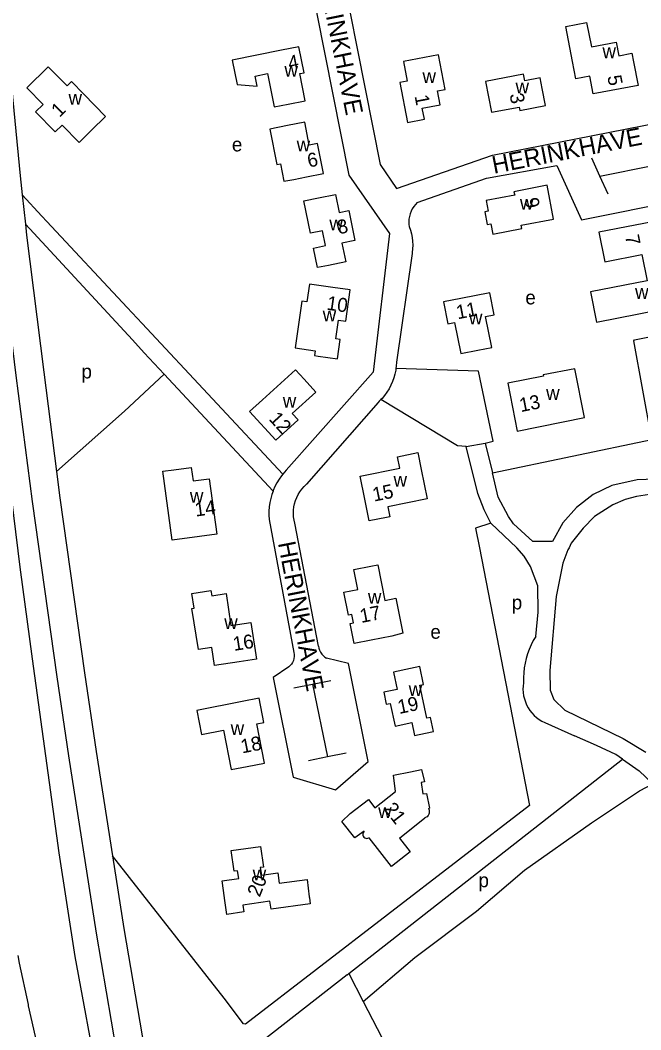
# Model space of a CAD drawing. Extents: x 157646 to 159241, y 379213 to 381217.
# Drawn here: x 158061.7 to 158238.9, y 379962.3 to 380250.8 of the extents above; entities that cross this region are included whole.
import ezdxf

# ---------------------------------------------------------------- set-up
doc = ezdxf.new("R2010")
doc.units = 0
for name, color, linetype in [('BLT_Basislijn', 7, 'Continuous'), ('BLT_Bebouwing', 7, 'Continuous'), ('BLT_Centroide', 7, 'Continuous'), ('BLT_Huisnummer', 7, 'Continuous'), ('BLT_Spoorlijn', 7, 'Continuous'), ('BLT_Straatnaam', 7, 'Continuous')]:
    doc.layers.add(name, color=color, linetype=linetype)

msp = doc.modelspace()

# ---------------------------------------------------------------- linework, layer by layer
at = {"layer": 'BLT_Basislijn'}
for p, q in [((158227.22, 380206.29), (158224.91, 380211.44)), ((158227.22, 380206.29), (158242.34, 380209.26)), ((158229.53, 380201.14), (158227.22, 380206.29)), ((158062.28, 380200.88), (158067.86, 380194.86)), ((158063.19, 380192.51), (158093.73, 380159.46)), ((158173.6, 380184.14), (158169.11, 380153.05)), ((158096.52, 380164.1), (158092.22, 380168.71)), ((158096.52, 380164.1), (158136.64, 380121.05)), ((158093.73, 380159.46), (158097.13, 380155.79)), ((158097.13, 380155.79), (158102.75, 380149.7)), ((158102.75, 380149.7), (158133.89, 380116.21)), ((158163.86, 380141.58), (158143.41, 380118.21)), ((158189.01, 380128.98), (158194.49, 380129.98)), ((158194.49, 380129.98), (158196.52, 380121.45)), ((158132.79, 380108.13), (158139.85, 380070.1)), ((158146.87, 380071.93), (158140.11, 380107.03)), ((158139.84, 380060.01), (158145.12, 380061.08)), ((158145.12, 380061.08), (158150.41, 380062.15)), ((158145.12, 380061.08), (158149.41, 380040.26)), ((158211.45, 380050.09), (158219.92, 380046.29)), ((158149.41, 380040.26), (158144.04, 380039.15)), ((158154.78, 380041.37), (158149.41, 380040.26)), ((158155.49, 379978.39), (158233.7, 380039.58)), ((158155.01, 379978.02), (158155.49, 379978.39)), ((158155.49, 379978.39), (158159.66, 379970.33))]:
    msp.add_line(p, q, dxfattribs=at)
for points in [[(158240.91, 380309.41), (158153.5, 380292.29), (158150.86, 380290.66), (158149.82, 380288.98), (158149.37, 380286.11), (158164.48, 380209.59), (158169.09, 380202.74), (158196.52, 380212.25), (158244.17, 380221.61), (158245.75, 380221.43)], [(158069.03, 380277.5), (158083.13, 380279.81), (158136.26, 380289.77), (158137.69, 380289.51), (158139.57, 380287.29), (158155.57, 380206.56), (158167.15, 380189.83), (158162.48, 380150.24), (158137.6, 380122.25), (158136.64, 380121.05)], [(158043.52, 380272.26), (158043.86, 380272.1), (158045.23, 380270.58), (158046.3, 380268.97), (158047.18, 380265.9), (158048.5, 380256.56), (158050.97, 380233.98), (158053.72, 380205.54), (158055.59, 380188.47), (158060.48, 380149.25), (158065.1, 380113.27), (158072.13, 380063.15), (158075.51, 380040.61), (158083.37, 379989.94), (158090.54, 379947.99)], [(158026.51, 380266.17), (158028.27, 380266.84), (158030.04, 380266.89), (158032.44, 380266.09), (158034.37, 380265.02), (158036.46, 380263.3), (158038.06, 380261.59), (158039.72, 380259.45), (158040.69, 380257.15), (158041.27, 380254.63), (158042.46, 380248.09), (158043.78, 380238.44), (158049.4, 380191.53), (158053.5, 380162.19), (158056.77, 380134.16), (158061.6, 380094.53), (158065.06, 380068.3), (158072.73, 380012.87), (158077.32, 379983.19), (158084.04, 379946.64)], [(158057.05, 380251.88), (158058.92, 380234.8), (158061.68, 380206.36), (158062.28, 380200.88)], [(158175.08, 380198.75), (158194.87, 380205.7), (158214.96, 380209.27)], [(158214.96, 380209.27), (158221.94, 380193.81), (158249.9, 380199.36)], [(158062.28, 380200.88), (158063.19, 380192.51)], [(158175.08, 380198.75), (158174.54, 380198.19), (158174.06, 380197.58), (158173.64, 380196.92), (158173.29, 380196.22), (158173.02, 380195.49), (158172.82, 380194.74), (158172.7, 380193.97), (158172.66, 380193.19), (158172.7, 380192.41), (158172.77, 380191.88)], [(158063.19, 380192.51), (158063.53, 380189.4), (158068.42, 380150.25), (158072.06, 380121.85)], [(158172.77, 380191.88), (158173.13, 380190.85), (158173.41, 380189.8), (158173.62, 380188.73), (158173.74, 380187.65), (158173.79, 380186.56), (158173.75, 380185.48), (158173.64, 380184.4), (158173.6, 380184.14)], [(158252.02, 380188.88), (158254.72, 380189.05), (158267, 380174.97), (158276.24, 380134.94), (158276.4, 380131.39), (158275.6, 380128.08), (158274.74, 380126.06), (158271.38, 380122.59), (158269.65, 380121.6), (158265.83, 380120.49), (158237.83, 380119.46), (158230.6, 380117.88), (158225.26, 380115.24), (158220.55, 380111.55), (158216.66, 380107.13), (158213.64, 380101.81), (158208.07, 380101.88), (158202.57, 380106.87), (158201.14, 380108.94), (158198.2, 380114.5), (158196.52, 380121.45)], [(158196.52, 380121.45), (158242.06, 380130.99), (158236.87, 380159.15), (158237.09, 380159.44), (158256.73, 380163.42), (158252.02, 380188.88)], [(158169.11, 380153.05), (158169.04, 380151.92), (158168.96, 380151.28)], [(158168.96, 380151.28), (158168.9, 380150.79), (158168.67, 380149.68), (158168.37, 380148.59), (158167.98, 380147.53), (158167.53, 380146.49), (158167, 380145.49), (158166.41, 380144.53), (158165.74, 380143.61), (158165.02, 380142.74), (158164.69, 380142.4)], [(158194.49, 380129.98), (158196.78, 380130.51), (158192.51, 380150.53), (158168.96, 380151.28)], [(158072.06, 380121.85), (158091.43, 380139.11), (158102.75, 380149.7)], [(158164.69, 380142.4), (158164.23, 380141.92), (158163.86, 380141.58)], [(158189.01, 380128.98), (158186.53, 380129.2), (158164.69, 380142.4)], [(158196.11, 380107.12), (158194.17, 380110.84), (158192.32, 380115.56), (158189.01, 380128.98)], [(158072.06, 380121.85), (158073.03, 380114.33), (158080.05, 380064.3), (158083.42, 380041.81), (158088.04, 380011.99)], [(158136.64, 380121.05), (158136.29, 380120.61), (158135.6, 380119.62), (158134.98, 380118.59), (158134.43, 380117.52), (158133.96, 380116.41), (158133.89, 380116.21)], [(158140.11, 380107.03), (158139.9, 380107.95), (158139.77, 380108.88), (158139.72, 380109.83), (158139.75, 380110.77), (158139.86, 380111.71), (158140.05, 380112.63), (158140.32, 380113.54), (158140.66, 380114.42), (158141.08, 380115.26), (158141.57, 380116.07), (158142.12, 380116.84), (158142.74, 380117.55), (158143.41, 380118.21)], [(158133.89, 380116.21), (158133.56, 380115.28), (158133.23, 380114.12), (158132.98, 380112.94), (158132.81, 380111.75), (158132.72, 380110.55), (158132.71, 380109.34), (158132.79, 380108.13)], [(158258.47, 380113.78), (158249.44, 380115.32), (158243.87, 380115.64), (158237.7, 380114.73), (158234.45, 380113.83), (158230.89, 380112.35), (158225.71, 380109), (158222.48, 380105.68), (158219.05, 380101.4), (158218.42, 380100), (158218.07, 380099.46), (158216.63, 380095.66), (158214.74, 380086.13), (158212.9, 380064.97), (158212.98, 380059.38), (158214.1, 380056.68), (158217.18, 380053.65), (158233.88, 380045.54), (158240.33, 380041.62)], [(158196.11, 380107.12), (158191.69, 380105.69), (158192.81, 380100), (158207.1, 380026.36), (158126.05, 379963.89), (158125.42, 379963.95), (158119.92, 379971.36), (158088.04, 380011.99)], [(158208.88, 380074.7), (158209.56, 380081.61), (158209.48, 380089.12), (158207.36, 380094.68), (158205.63, 380097.68), (158203.48, 380100), (158196.11, 380107.12)], [(158146.87, 380071.93), (158146.99, 380071.33), (158147.18, 380070.74), (158147.45, 380070.19), (158147.79, 380069.68), (158148.19, 380069.21), (158148.64, 380068.8), (158149.15, 380068.46)], [(158208.88, 380074.7), (158208.2, 380073.5), (158207.58, 380072.27), (158207.03, 380071), (158206.56, 380069.71), (158206.17, 380068.39), (158205.85, 380067.05), (158205.61, 380065.69), (158205.45, 380064.32), (158205.37, 380062.94), (158205.36, 380061.56), (158205.37, 380061.43)], [(158139.85, 380070.1), (158139.93, 380069.53), (158139.93, 380068.95), (158139.85, 380068.38), (158139.68, 380067.83), (158139.45, 380067.3), (158139.15, 380066.81), (158138.77, 380066.37), (158138.35, 380065.98)], [(158138.35, 380065.98), (158133.92, 380063), (158139.6, 380034.49), (158151.73, 380030.89), (158161.02, 380038.94), (158155.39, 380067), (158149.15, 380068.46)], [(158205.37, 380061.43), (158205.26, 380060.51), (158205.24, 380059.59), (158205.3, 380058.67), (158205.43, 380057.75), (158205.64, 380056.86), (158205.93, 380055.98), (158206.3, 380055.13), (158206.74, 380054.32), (158207.24, 380053.55), (158207.82, 380052.83), (158208.45, 380052.15), (158209.13, 380051.54), (158209.87, 380050.98), (158210.65, 380050.5), (158211.45, 380050.09)], [(158233.7, 380039.58), (158231.75, 380040.93), (158226.29, 380043.51), (158219.92, 380046.29)], [(158233.7, 380039.58), (158238.4, 380036.33), (158242.35, 380032.59)], [(158159.66, 379970.33), (158174.35, 379982.97), (158191.97, 379996.18), (158205.72, 380007.86), (158224.81, 380021.43), (158238.51, 380030.61), (158242.35, 380032.59)], [(158088.04, 380011.99), (158091.26, 379991.23), (158098.41, 379949.44), (158101.11, 379935.8)], [(158072.5, 379932.76), (158071.31, 379937.57), (158070.15, 379942.39), (158069.57, 379944.86), (158067.13, 379955.38), (158066.77, 379956.99), (158064.09, 379969.16), (158064.01, 379969.53), (158061.53, 379981.35), (158061.1, 379983.47)], [(158155.01, 379978.02), (158101.11, 379935.8)], [(158159.66, 379970.33), (158186.48, 379918.51), (158201.95, 379874.84), (158218.42, 379836.26)]]:
    msp.add_lwpolyline(points, dxfattribs=at)
at = {"layer": 'BLT_Bebouwing'}
for p, q in [((158112.87, 380103.23), (158105.07, 380102.17)), ((158170, 380017.04), (158177.23, 380022.87))]:
    msp.add_line(p, q, dxfattribs=at)
for points in [[(158236.85, 380238.9), (158238.13, 380232.21), (158225.27, 380229.74), (158224.3, 380234.84), (158220.37, 380234.08), (158219.42, 380238.99), (158217.5, 380249.03), (158223.43, 380250.17), (158224.77, 380243.18), (158231.87, 380244.54), (158232.62, 380240.66), (158236.37, 380241.38), (158236.85, 380238.9)], [(158138.19, 380226.84), (158143.09, 380227.82), (158141.55, 380235.56), (158142.73, 380235.8), (158141.24, 380243.24), (158136.34, 380242.26), (158122.25, 380239.45), (158123.66, 380232.42), (158129.39, 380231.93), (158128.81, 380234.88), (158132.34, 380235.59), (158134.24, 380226.05), (158138.19, 380226.84)], [(158171.13, 380238.99), (158172.2, 380233.43), (158170.07, 380233.02), (158172.25, 380221.62), (158177.09, 380222.55), (158176.49, 380225.67), (158181.62, 380226.65), (158180.85, 380230.65), (158183.03, 380231.07), (158181.14, 380240.91), (158171.13, 380238.99)], [(158082.08, 380219.39), (158078.5, 380215.9), (158073.65, 380220.85), (158071.66, 380218.89), (158066.05, 380224.62), (158068.24, 380226.76), (158063.6, 380231.49), (158069.71, 380237.48), (158075.05, 380232.03), (158076.33, 380233.28), (158079.82, 380229.71), (158086.08, 380223.32), (158082.08, 380219.39)], [(158210.76, 380231.35), (158210.18, 380234.32), (158205.76, 380233.47), (158205.39, 380235.4), (158194.57, 380233.32), (158196.26, 380224.5), (158204.17, 380226.02), (158204.36, 380225.03), (158211.7, 380226.44), (158210.76, 380231.35)], [(158143.39, 380206.03), (158148.3, 380207.01), (158146.58, 380215.63), (158144.23, 380215.16), (158142.93, 380221.67), (158138.03, 380220.69), (158132.94, 380219.68), (158134.96, 380209.56), (158136.01, 380209.77), (158137, 380204.78), (158139.81, 380205.32), (158143.39, 380206.03)], [(158214.01, 380194.01), (158212.16, 380203.64), (158202.68, 380201.82), (158202.88, 380200.83), (158194.76, 380199.27), (158195.35, 380196.21), (158194.36, 380196.02), (158195.05, 380192.45), (158196.06, 380192.65), (158196.63, 380189.69), (158204.93, 380191.28), (158204.75, 380192.24), (158214.01, 380194.01)], [(158149.74, 380180.76), (158146.55, 380180.11), (158145.41, 380185.71), (158148.87, 380186.42), (158148.01, 380190.62), (158144.58, 380189.92), (158142.72, 380199.22), (158146.84, 380200.04), (158151.75, 380201.02), (158152.77, 380195.9), (158155.51, 380196.45), (158157.23, 380187.83), (158153.56, 380187.08), (158154.64, 380181.76), (158149.74, 380180.76)], [(158246.1, 380188.86), (158245.14, 380193.77), (158226.94, 380190.21), (158228.6, 380181.74), (158239.23, 380183.82), (158240.7, 380176.33), (158224.56, 380173.18), (158226.24, 380164.57), (158249.94, 380169.21), (158246.1, 380188.86)], [(158152.25, 380154.03), (158153.05, 380159.6), (158151.84, 380159.77), (158152.61, 380165.13), (158154.66, 380164.84), (158155.94, 380173.73), (158150.99, 380174.44), (158144.29, 380175.41), (158143.55, 380170.31), (158142.11, 380170.51), (158140.2, 380157.19), (158145.91, 380156.37), (158145.71, 380154.97), (158146.77, 380154.81), (158152.25, 380154.03)], [(158192.37, 380156.51), (158196.33, 380157.24), (158194.59, 380166.15), (158197.04, 380166.63), (158195.82, 380172.9), (158187.5, 380171.27), (158182.59, 380170.31), (158183.81, 380164.09), (158185.72, 380164.46), (158187.46, 380155.55), (158192.37, 380156.51)], [(158142.77, 380148.22), (158140.34, 380150.91), (158130.9, 380142.36), (158127.2, 380139.01), (158134.64, 380130.79), (158141.04, 380136.59), (158139.39, 380138.41), (158146.13, 380144.51), (158142.77, 380148.22)], [(158211.01, 380149.46), (158211.08, 380149.09), (158200.95, 380147.11), (158203.62, 380133.39), (158222.84, 380137.25), (158220.1, 380151.23), (158211.01, 380149.46)], [(158176.2, 380122.37), (158177.9, 380114.06), (158166.64, 380111.76), (158167.22, 380108.91), (158166.25, 380108.71), (158161.35, 380107.71), (158160.08, 380113.97), (158158.77, 380120.48), (158170.06, 380122.78), (158169.39, 380126.08), (158175.2, 380127.27), (158176.2, 380122.37)], [(158105.07, 380102.17), (158102.44, 380121.9), (158105.59, 380122.33), (158110.54, 380123.01), (158111.07, 380119.15), (158115.66, 380119.78), (158117.83, 380103.9), (158112.87, 380103.23)], [(158161.94, 380073.64), (158157.03, 380072.68), (158155.91, 380078.36), (158156.84, 380078.55), (158156.36, 380081), (158155.43, 380080.82), (158154.13, 380087.39), (158158.06, 380088.16), (158156.95, 380093.85), (158161.85, 380094.81), (158163.81, 380095.2), (158165.82, 380084.99), (158168.95, 380085.61), (158170.91, 380075.6), (158167.82, 380074.79), (158161.94, 380073.64)], [(158116.15, 380087.84), (158116.39, 380086.32), (158120.46, 380086.95), (158121.87, 380077.83), (158127.55, 380078.71), (158129.17, 380068.22), (158124.23, 380067.45), (158117.17, 380066.36), (158116.37, 380071.53), (158112.55, 380070.93), (158110.74, 380082.66), (158111.35, 380082.76), (158110.7, 380087), (158116.15, 380087.84)], [(158179.2, 380047.4), (158179.73, 380047.51), (158178.87, 380051.54), (158177.8, 380051.32), (158175.79, 380060.75), (158176.89, 380060.98), (158175.79, 380066.13), (158173.16, 380065.57), (158168.27, 380064.53), (158169.33, 380059.55), (158165.48, 380058.73), (158166.21, 380055.3), (158167.36, 380055.54), (158168.74, 380049.05), (158173.52, 380050.07), (158174.31, 380046.36), (158179.2, 380047.4)], [(158126.51, 380037.56), (158131.42, 380038.52), (158129.23, 380049.68), (158131.3, 380050.09), (158129.94, 380057.02), (158125.04, 380056.06), (158112.16, 380053.54), (158113.49, 380046.71), (158119.77, 380047.93), (158121.97, 380036.67), (158126.51, 380037.56)], [(158159.86, 380019.02), (158157.23, 380017.16), (158153.57, 380021.84), (158155.9, 380024.09), (158161.1, 380028.14), (158162.98, 380025.74), (158168.89, 380030.35), (158168.24, 380035.01), (158173.13, 380036.03), (158176.31, 380036.69), (158177.14, 380033.11), (158176.21, 380032.98), (158176.66, 380029.7), (158177.69, 380029.85), (158178.58, 380025.59)], [(158177.95, 380023.18), (158177.62, 380023), (158177.23, 380022.87)], [(158177.95, 380023.18), (158178.14, 380023.39), (158178.31, 380023.65), (158178.46, 380023.97), (158178.55, 380024.3), (158178.59, 380024.61), (158178.58, 380024.91), (158178.51, 380025.28), (158178.41, 380025.57), (158178.58, 380025.59)], [(158159.86, 380019.02), (158159.67, 380018.77), (158159.55, 380018.48), (158159.51, 380018.18), (158159.55, 380017.87), (158159.66, 380017.58), (158159.85, 380017.34), (158160.09, 380017.14), (158160.38, 380017.02), (158160.68, 380016.97), (158160.99, 380017), (158161.28, 380017.11), (158161.33, 380017.15)], [(158170, 380017.04), (158173.06, 380013.12), (158167.72, 380008.96), (158164.41, 380013.2), (158161.33, 380017.15)], [(158144.23, 380000.25), (158144.27, 380000), (158144.49, 379998.24), (158133.32, 379996.8), (158132.99, 379999.03), (158125.27, 379997.88), (158125.55, 379995.99), (158120.71, 379995.27), (158120.02, 379999.86), (158120, 380000), (158119.33, 380004.81), (158124.07, 380005.47), (158123.76, 380007.71), (158122.76, 380007.57), (158121.93, 380013.54), (158130.34, 380014.71), (158131.17, 380008.79), (158130.24, 380008.66), (158130.55, 380006.49), (158135.25, 380007.15), (158135.63, 380004.19), (158143.6, 380005.21), (158144.23, 380000.25)]]:
    msp.add_lwpolyline(points, dxfattribs=at)
at = {"layer": 'BLT_Spoorlijn'}
msp.add_lwpolyline([(158067.86, 380194.86), (158069.33, 380193.28), (158092.22, 380168.71)], dxfattribs=at)

# ---------------------------------------------------------------- texts
at = {"layer": 'BLT_Centroide'}
for s, p in [('w', (158227.94, 380239.97)), ('w', (158137.13, 380234.66)), ('w', (158176.55, 380232.86)), ('w', (158203.12, 380229.94)), ('w', (158075.48, 380226.69)), ('e', (158122.14, 380213.33)), ('w', (158140.62, 380213.34)), ('w', (158204.38, 380196.66)), ('w', (158149.97, 380190.73)), ('w', (158237.25, 380171.19)), ('e', (158205.93, 380169.6)), ('w', (158148.06, 380164.75)), ('w', (158189.81, 380163.86)), ('p', (158079.19, 380148.44)), ('w', (158211.86, 380142.31)), ('w', (158136.66, 380140.11)), ('w', (158168.29, 380117.5)), ('w', (158110.14, 380112.89)), ('w', (158160.97, 380084.05)), ('p', (158202.05, 380082.43)), ('w', (158119.94, 380076.83)), ('e', (158178.82, 380074.04)), ('w', (158172.61, 380057.67)), ('w', (158121.78, 380046.53)), ('w', (158163.9, 380022.81)), ('w', (158128.07, 380005)), ('p', (158192.55, 380003.03))]:
    msp.add_text(s, height=4, dxfattribs=at).set_placement(p)
at = {"layer": 'BLT_Huisnummer'}
for s, rotation, p in [('4', 11.2695, (158138.57, 380236.6)), ('5', 280.8525, (158229.32, 380234.76)), ('1', 280.8548, (158174.28, 380229.16)), ('3', 280.8696, (158201.4, 380229.6)), ('1', 44.4005, (158072.9, 380222.87)), ('6', 11.2695, (158144.09, 380208.69)), ('9', 280.8456, (158205.65, 380199.74)), ('8', 11.2695, (158152.67, 380189.64)), ('7', 281.056, (158234.38, 380189.14)), ('10', 351.8208, (158149.03, 380168.12)), ('11', 11.0582, (158186.59, 380165.33)), ('13', 11.0565, (158204.62, 380138.81)), ('12', 312.1666, (158132.5, 380136.74)), ('15', 11.5183, (158162.71, 380113.22)), ('14', 7.759, (158111.79, 380108.95)), ('17', 11.0886, (158159.07, 380078.54)), ('16', 8.798, (158122.72, 380070.55)), ('19', 11.99, (158169.9, 380052.51)), ('18', 11.0717, (158125.06, 380041.25)), ('21', 307.9494, (158165.34, 380025.35)), ('20', 68.4647, (158130.07, 380000))]:
    msp.add_text(s, height=4, rotation=rotation, dxfattribs=at).set_placement(p)
at = {"layer": 'BLT_Straatnaam'}
for rotation, p in [(281.3959, (158146.17, 380265.97)), (11.1829, (158196.94, 380206.91)), (281.0246, (158135.26, 380101.38))]:
    msp.add_text('HERINKHAVE', height=5, rotation=rotation, dxfattribs=at).set_placement(p)

doc.saveas('drawing.dxf')
